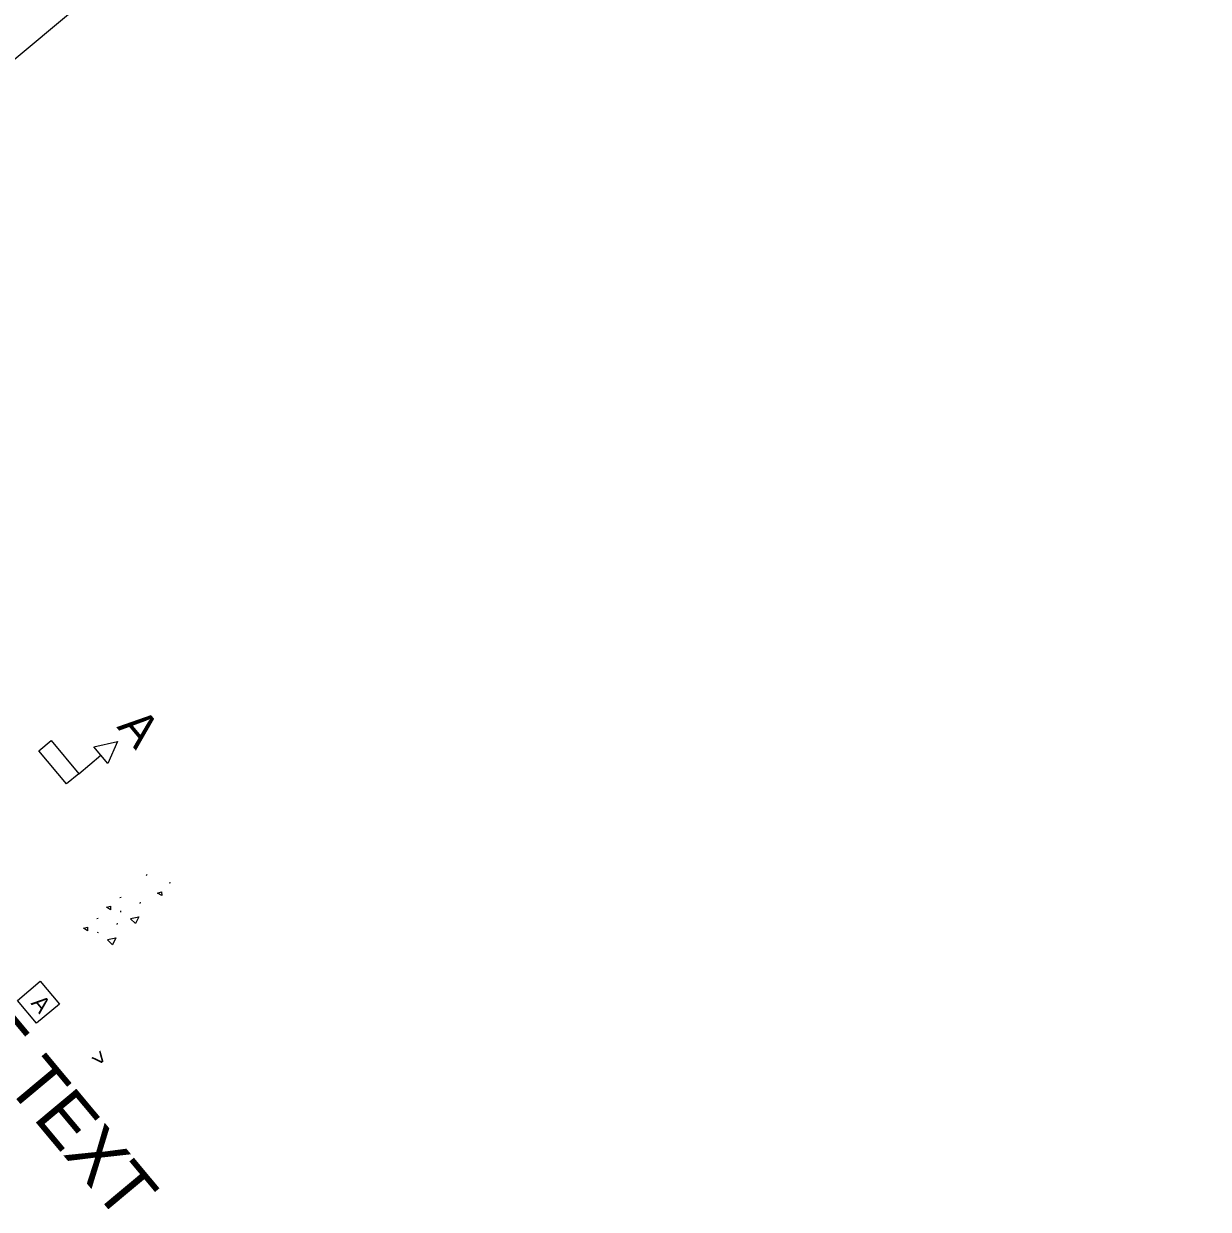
# Model space of a CAD drawing. Extents: x 2042995 to 2043795, y 305365 to 306249.
# Drawn here: x 2043611.9 to 2043794.6, y 305365.4 to 305548.1 of the extents above; entities that cross this region are included whole.
import ezdxf

# ---------------------------------------------------------------- set-up
doc = ezdxf.new("R2010")
doc.units = 0
for name, color, linetype in [('BR_CENTER LINES', 7, 'Continuous'), ('BR_TABLE LINES', 7, 'Continuous'), ('BR_TEXT', 7, 'Continuous'), ('RD_SHT_IplotShp', 7, 'Continuous')]:
    doc.layers.add(name, color=color, linetype=linetype)

msp = doc.modelspace()

# ---------------------------------------------------------------- linework, layer by layer
at = {"layer": 'BR_CENTER LINES'}
for p, q in [((2043630.97, 305416.99), (2043630.83, 305416.84)), ((2043634.36, 305415.7), (2043634.58, 305415.76)), ((2043626.75, 305413.47), (2043626.97, 305413.53)), ((2043629.87, 305412.72), (2043629.81, 305412.56)), ((2043623.21, 305410.23), (2043623.42, 305410.29)), ((2043626.88, 305411.38), (2043626.83, 305411.22)), ((2043623.34, 305408.14), (2043623.3, 305407.98)), ((2043626.32, 305409.48), (2043626.27, 305409.32))]:
    msp.add_line(p, q, dxfattribs=at)
for points in [[(2043632.58, 305414.15), (2043633.18, 305414.31), (2043633.21, 305413.75), (2043632.58, 305414.15)], [(2043624.7, 305411.96), (2043625.3, 305412.12), (2043625.33, 305411.55), (2043624.7, 305411.96)], [(2043628.39, 305410.2), (2043629.66, 305410.47), (2043629.15, 305409.44), (2043628.41, 305410.18)], [(2043621.16, 305408.73), (2043621.76, 305408.87), (2043621.79, 305408.32), (2043621.16, 305408.73)], [(2043624.85, 305406.97), (2043626.12, 305407.24), (2043625.61, 305406.19), (2043624.86, 305406.95)]]:
    msp.add_lwpolyline(points, dxfattribs=at)
at = {"layer": 'BR_TABLE LINES'}
msp.add_line((2043620.42, 305432.54), (2043623.83, 305435.39), dxfattribs=at)
for points in [[(2043614.27, 305436.09), (2043616.14, 305437.66), (2043620.42, 305432.54), (2043618.54, 305430.98)], [(2043622.76, 305436.67), (2043626.39, 305437.53), (2043624.9, 305434.11)]]:
    msp.add_lwpolyline(points, close=True, dxfattribs=at)
at = {"layer": 'BR_TEXT'}
msp.add_lwpolyline([(2043614.49, 305400.55), (2043617.44, 305397.02), (2043613.91, 305394.07), (2043610.96, 305397.6)], close=True, dxfattribs=at)
at = {"layer": 'RD_SHT_IplotShp'}
msp.add_lwpolyline([(2043333.03, 306249), (2043794.57, 305696.38), (2043456.86, 305414.33), (2042995.32, 305966.94)], close=True, dxfattribs=at)

# ---------------------------------------------------------------- texts
at = {"layer": 'BR_TEXT'}
for s, height, p in [('STANDARD TITLE TEXT', 8.1251, (2043547.84, 305457.76)), ('A', 5.31, (2043626.2, 305439.72)), ('A', 2.5, (2043612.95, 305397.12)), ('>', 2.5, (2043622.03, 305388.66))]:
    msp.add_text(s, height=height, rotation=309.8684, dxfattribs=at).set_placement(p)

doc.saveas('drawing.dxf')
